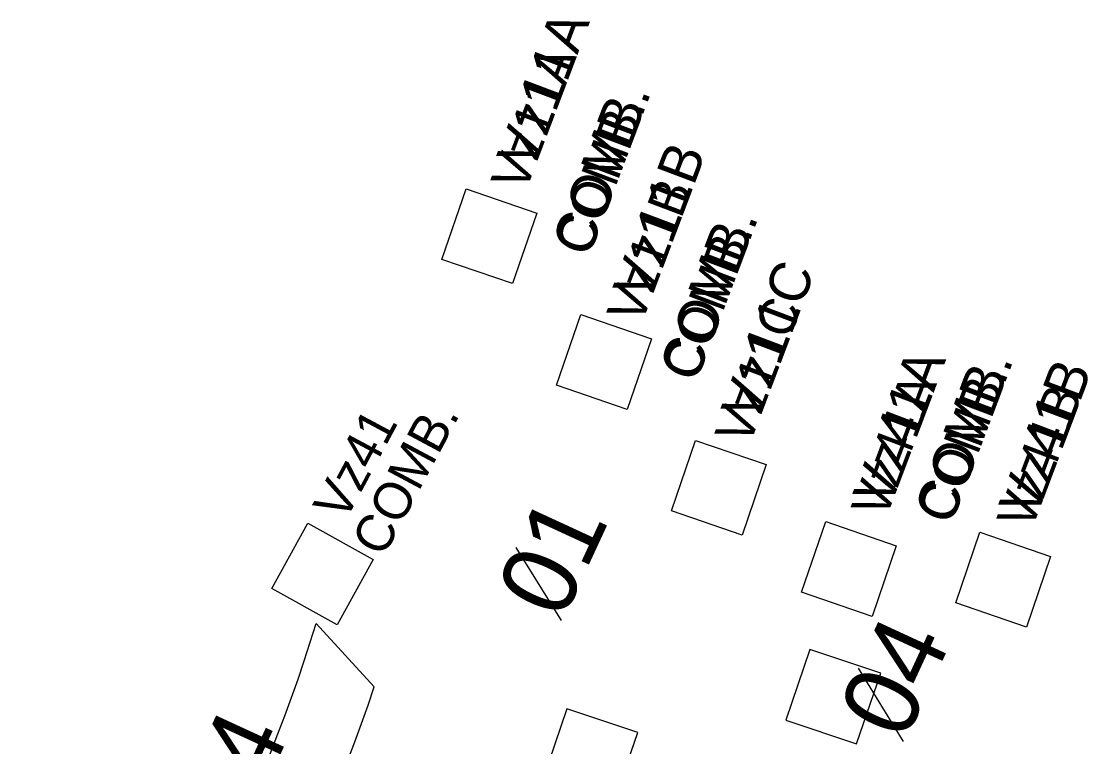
# Model space of a CAD drawing. Extents: x 647787 to 668496, y 640478 to 654412.
# Drawn here: x 661818.9 to 661904.6, y 647448.9 to 647507.2 of the extents above; entities that cross this region are included whole.
import ezdxf

# ---------------------------------------------------------------- set-up
doc = ezdxf.new("R2010")
doc.units = 0
for name, color, linetype in [('Default', 7, 'Continuous'), ('TEMP_DETECTION ZONE_Stage 2', 7, 'Continuous'), ('TEMP_DETECTION ZONE_STAGE 3', 7, 'Continuous'), ('TEMP_DETECTION_ZONE_STAGE 4', 7, 'Continuous'), ('TEMP_DETECTION_ZONE_STAGE 5', 7, 'Continuous'), ('TEMP_SIGNAL_POLES_STAGE 1B', 7, 'Continuous')]:
    doc.layers.add(name, color=color, linetype=linetype)

msp = doc.modelspace()

# ---------------------------------------------------------------- linework, layer by layer
at = {"layer": 'Default'}
for p, q in [((661858.61, 647464.882), (661862.234, 647458.998)), ((661858.61, 647464.882), (661862.234, 647458.998)), ((661886.097, 647455.167), (661889.721, 647449.282)), ((661886.097, 647455.167), (661889.721, 647449.282))]:
    msp.add_line(p, q, dxfattribs=at)
at = {"layer": 'TEMP_DETECTION ZONE_Stage 2'}
msp.add_lwpolyline([(661838.987, 647461.577), (661841.894, 647466.826), (661847.142, 647463.919), (661844.235, 647458.67)], close=True, dxfattribs=at)
at = {"layer": 'TEMP_DETECTION ZONE_STAGE 3'}
for points in [[(661838.987, 647461.577), (661841.894, 647466.826), (661847.142, 647463.919), (661844.235, 647458.67)], [(661882.225, 647456.682), (661880.278, 647451.007), (661885.97, 647449.107), (661887.916, 647454.783)], [(661882.225, 647456.682), (661880.278, 647451.007), (661885.97, 647449.107), (661887.916, 647454.783)], [(661882.225, 647456.682), (661880.278, 647451.007), (661885.97, 647449.107), (661887.916, 647454.783)], [(661882.227, 647456.684), (661880.28, 647451.009), (661885.972, 647449.109), (661887.919, 647454.785)]]:
    msp.add_lwpolyline(points, close=True, dxfattribs=at)
at = {"layer": 'TEMP_DETECTION_ZONE_STAGE 4'}
for points in [[(661838.987, 647461.577), (661841.894, 647466.826), (661847.142, 647463.919), (661844.235, 647458.67)], [(661862.703, 647451.916), (661860.756, 647446.241), (661866.447, 647444.341), (661868.394, 647450.017)], [(661862.703, 647451.916), (661860.756, 647446.241), (661866.447, 647444.341), (661868.394, 647450.017)], [(661862.703, 647451.916), (661860.756, 647446.241), (661866.447, 647444.341), (661868.394, 647450.017)], [(661862.705, 647451.918), (661860.758, 647446.243), (661866.45, 647444.343), (661868.397, 647450.019)]]:
    msp.add_lwpolyline(points, close=True, dxfattribs=at)
at = {"layer": 'TEMP_DETECTION_ZONE_STAGE 5'}
msp.add_line((661842.552, 647458.762), (661847.229, 647453.681), dxfattribs=at)
for points in [[(661852.657, 647488.026), (661854.601, 647493.703), (661860.277, 647491.758), (661858.333, 647486.082)], [(661861.877, 647477.915), (661863.822, 647483.592), (661869.498, 647481.647), (661867.554, 647475.971)], [(661871.101, 647467.811), (661873.045, 647473.488), (661878.721, 647471.543), (661876.777, 647465.867)], [(661881.547, 647461.278), (661883.491, 647466.954), (661889.168, 647465.009), (661887.223, 647459.333)], [(661893.941, 647460.43), (661895.886, 647466.106), (661901.562, 647464.162), (661899.617, 647458.486)]]:
    msp.add_lwpolyline(points, close=True, dxfattribs=at)
for radius, start, end in [(124, 319.96797, 343.07215), (130, 319.49323, 341.52977)]:
    msp.add_arc((661723.925, 647494.867), radius, start, end, dxfattribs=at)
at = {"layer": 'TEMP_SIGNAL_POLES_STAGE 1B'}
msp.add_line((661842.552, 647458.762), (661847.229, 647453.681), dxfattribs=at)
for points in [[(661852.657, 647488.026), (661854.601, 647493.703), (661860.277, 647491.758), (661858.333, 647486.082)], [(661861.877, 647477.915), (661863.822, 647483.592), (661869.498, 647481.647), (661867.554, 647475.971)], [(661871.101, 647467.811), (661873.045, 647473.488), (661878.721, 647471.543), (661876.777, 647465.867)], [(661881.547, 647461.278), (661883.491, 647466.954), (661889.168, 647465.009), (661887.223, 647459.333)], [(661893.941, 647460.43), (661895.886, 647466.106), (661901.562, 647464.162), (661899.617, 647458.486)]]:
    msp.add_lwpolyline(points, close=True, dxfattribs=at)
for radius, start, end in [(124, 319.96797, 343.07215), (130, 319.49323, 341.52977)]:
    msp.add_arc((661723.925, 647494.867), radius, start, end, dxfattribs=at)

# ---------------------------------------------------------------- texts
at = {"layer": 'Default'}
for s, p in [('01', (661862.346, 647458.901)), ('01', (661862.346, 647458.901)), ('04', (661889.833, 647449.185)), ('04', (661889.833, 647449.185)), ('04', (661836.651, 647441.674)), ('04', (661836.651, 647441.674)), ('04', (661836.651, 647441.674))]:
    msp.add_text(s, height=6, rotation=65.21411, dxfattribs=at).set_placement(p)
at = {"layer": 'TEMP_DETECTION ZONE_Stage 2'}
for s, p in [('Vz41', (661844.854, 647466.845)), ('COMB.', (661847.941, 647464.002))]:
    msp.add_text(s, height=3, rotation=61.85605, dxfattribs=at).set_placement(p)
at = {"layer": 'TEMP_DETECTION ZONE_STAGE 3'}
for s, p in [('Vz41', (661844.854, 647466.845)), ('COMB.', (661847.941, 647464.002))]:
    msp.add_text(s, height=3, rotation=61.85605, dxfattribs=at).set_placement(p)
at = {"layer": 'TEMP_DETECTION_ZONE_STAGE 4'}
for s, p in [('Vz41', (661844.854, 647466.845)), ('COMB.', (661847.941, 647464.002))]:
    msp.add_text(s, height=3, rotation=61.85605, dxfattribs=at).set_placement(p)
at = {"layer": 'TEMP_DETECTION_ZONE_STAGE 5'}
for s, p in [('Vz11A', (661859.341, 647493.311)), ('COMB.', (661864.454, 647488.128)), ('Vz11B', (661868.657, 647482.681)), ('COMB.', (661873.074, 647478.061)), ('Vz11C', (661877.333, 647472.939)), ('COMB.', (661893.563, 647466.604)), ('Vz41A', (661888.282, 647467.021)), ('Vz41B', (661899.986, 647466.111))]:
    msp.add_text(s, height=3, rotation=69.31862, dxfattribs=at).set_placement(p)
at = {"layer": 'TEMP_SIGNAL_POLES_STAGE 1B'}
for s, p in [('Vz11A', (661860.041, 647495.166)), ('COMB.', (661864.463, 647488.149)), ('Vz11B', (661869.381, 647484.597)), ('COMB.', (661873.082, 647478.083)), ('Vz11C', (661878.059, 647474.861)), ('Vz41A', (661888.657, 647468.014)), ('COMB.', (661893.571, 647466.625)), ('Vz41B', (661900.384, 647467.166))]:
    msp.add_text(s, height=3.25, rotation=69.31862, dxfattribs=at).set_placement(p)

doc.saveas('drawing.dxf')
